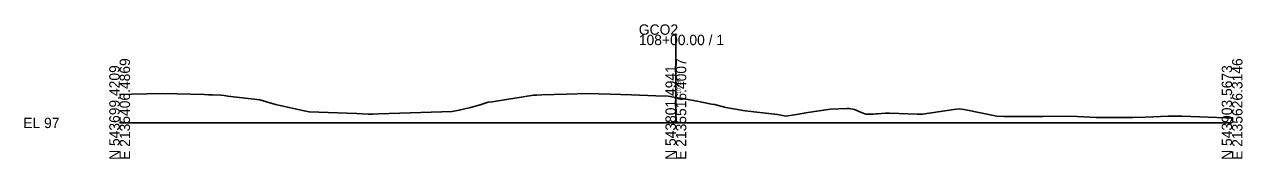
# Model space of a CAD drawing. Extents: x -14327 to 8886, y -10 to 39048.
# Drawn here: x 3974.3 to 4302.8, y 35990.3 to 36026.7 of the extents above; entities that cross this region are included whole.
import ezdxf

# ---------------------------------------------------------------- set-up
doc = ezdxf.new("R2010")
doc.units = 0
for name, color, linetype in [('RD_GPK_XS_Cell', 7, 'Continuous'), ('RD_XS_ExGround', 7, 'Continuous'), ('RD_XS_TX_Elev_EX', 7, 'Continuous')]:
    doc.layers.add(name, color=color, linetype=linetype)

msp = doc.modelspace()

# ---------------------------------------------------------------- linework, layer by layer
at = {"layer": 'RD_GPK_XS_Cell'}
for p, q in [((4150, 36000), (4150, 36023.85)), ((4000, 36000), (4150, 36000)), ((4150, 36000), (4300, 36000))]:
    msp.add_line(p, q, dxfattribs=at)
at = {"layer": 'RD_XS_ExGround'}
for p, q in [((4000, 36007.67), (4003.2, 36007.76)), ((4003.2, 36007.76), (4011.64, 36007.93)), ((4011.64, 36007.93), (4022.85, 36007.66)), ((4022.85, 36007.66), (4023.97, 36007.64)), ((4023.97, 36007.64), (4025.02, 36007.6)), ((4025.02, 36007.6), (4027.25, 36007.53)), ((4027.25, 36007.53), (4028.17, 36007.41)), ((4028.17, 36007.41), (4029.18, 36007.27)), ((4029.18, 36007.27), (4037.79, 36006.2)), ((4100.98, 36005.78), (4111.58, 36007.48)), ((4111.58, 36007.48), (4112.52, 36007.52)), ((4112.52, 36007.52), (4113.88, 36007.56)), ((4113.88, 36007.56), (4120.54, 36007.78)), ((4120.54, 36007.78), (4126.21, 36007.95)), ((4126.21, 36007.95), (4132.25, 36007.78)), ((4132.25, 36007.78), (4138, 36007.61)), ((4138, 36007.61), (4144.57, 36007.35)), ((4144.57, 36007.35), (4147.95, 36007.21)), ((4147.95, 36007.21), (4150, 36006.88)), ((4037.79, 36006.2), (4038.71, 36005.93)), ((4038.71, 36005.93), (4042.06, 36004.94)), ((4042.06, 36004.94), (4049.8, 36003.3)), ((4091.57, 36003.47), (4094.61, 36004.15)), ((4094.61, 36004.15), (4097.19, 36004.93)), ((4097.19, 36004.93), (4099.36, 36005.6)), ((4099.36, 36005.6), (4100.43, 36005.71)), ((4100.43, 36005.71), (4100.98, 36005.78)), ((4150, 36006.88), (4151.24, 36006.67)), ((4151.24, 36006.67), (4155.71, 36005.87)), ((4155.71, 36005.87), (4159.61, 36005.05)), ((4159.61, 36005.05), (4160.06, 36004.95)), ((4160.06, 36004.95), (4160.11, 36005.11)), ((4160.11, 36005.11), (4163.46, 36004.19)), ((4163.46, 36004.19), (4168.68, 36003.23)), ((4191.71, 36003.7), (4196.2, 36003.91)), ((4196.2, 36003.91), (4196.72, 36003.88)), ((4049.8, 36003.3), (4051.15, 36003)), ((4051.15, 36003), (4063.97, 36002.52)), ((4063.97, 36002.52), (4067.06, 36002.4)), ((4067.06, 36002.4), (4068.26, 36002.37)), ((4068.26, 36002.37), (4069.89, 36002.41)), ((4069.89, 36002.41), (4089.7, 36003.04)), ((4089.7, 36003.04), (4091.57, 36003.47)), ((4168.68, 36003.23), (4177.4, 36002.24)), ((4177.4, 36002.24), (4179.64, 36001.85)), ((4179.64, 36001.85), (4182.51, 36002.29)), ((4182.51, 36002.29), (4185.58, 36002.85)), ((4185.58, 36002.85), (4191.71, 36003.7)), ((4196.72, 36003.88), (4198.21, 36003.61)), ((4198.21, 36003.61), (4200.28, 36002.7)), ((4200.28, 36002.7), (4201.21, 36002.33)), ((4201.21, 36002.33), (4203.22, 36002.39)), ((4203.22, 36002.39), (4203.89, 36002.42)), ((4203.89, 36002.42), (4204.34, 36002.43)), ((4204.34, 36002.43), (4206.51, 36002.61)), ((4206.51, 36002.61), (4207.62, 36002.59)), ((4207.62, 36002.59), (4215.08, 36002.35)), ((4215.08, 36002.35), (4216.52, 36002.33)), ((4216.52, 36002.33), (4224.99, 36003.65)), ((4224.99, 36003.65), (4226.53, 36003.85)), ((4226.53, 36003.85), (4228.22, 36003.57)), ((4228.22, 36003.57), (4236.53, 36001.82)), ((4236.53, 36001.82), (4238.44, 36001.71)), ((4238.44, 36001.71), (4246.54, 36001.76)), ((4246.54, 36001.76), (4248.96, 36001.77)), ((4248.96, 36001.77), (4256.55, 36001.81)), ((4256.55, 36001.81), (4263.31, 36001.47)), ((4263.31, 36001.47), (4266.56, 36001.46)), ((4266.56, 36001.46), (4273.2, 36001.47)), ((4273.2, 36001.47), (4276.56, 36001.53)), ((4276.56, 36001.53), (4282.75, 36001.83)), ((4282.75, 36001.83), (4286.57, 36001.8)), ((4286.57, 36001.8), (4298.23, 36001.39)), ((4298.23, 36001.39), (4300, 36001.37))]:
    msp.add_line(p, q, dxfattribs=at)

# ---------------------------------------------------------------- texts
at = {"layer": 'RD_GPK_XS_Cell'}
for s, p in [('GCO2', (4140, 36023.85)), ('108+00.00 / 1', (4140, 36021.05)), ('EL 97', (3974, 35998.6))]:
    msp.add_text(s, height=2.8, dxfattribs=at).set_placement(p)
for s, p in [('E 2135406.4869', (4002.8, 35990)), ('E 2135516.4007', (4152.8, 35990)), ('E 2135626.3146', (4302.8, 35990)), ('N 543699.4209', (4000, 35990)), ('N 543801.4941', (4150, 35990)), ('N 543903.5673', (4300, 35990))]:
    msp.add_text(s, height=2.8, rotation=90, dxfattribs=at).set_placement(p)
at = {"layer": 'RD_XS_TX_Elev_EX'}
msp.add_text('103.88', height=1, rotation=90, dxfattribs=at).set_placement((4151.25, 36007.88))

doc.saveas('drawing.dxf')
